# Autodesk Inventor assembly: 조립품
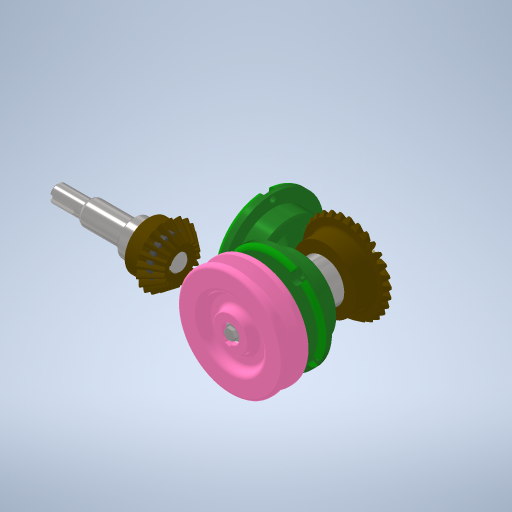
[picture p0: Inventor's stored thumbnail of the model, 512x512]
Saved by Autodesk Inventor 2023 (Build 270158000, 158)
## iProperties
Created: 2023-12
Part Number: 조립품
Document SubType Name: Assembly
Designer: asung
Author: asung
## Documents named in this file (15)
- C:\Users\asung\Desktop\시험\조립품.iam
- C:\Users\asung\Desktop\시험\본체.ipt
- C:\Users\asung\Desktop\시험\메인 축.ipt
- 메인 축.ipt
- C:\Users\asung\Desktop\시험\베어링 6203.ipt
- C:\Users\asung\Desktop\시험\커버.ipt
- C:\Users\asung\Desktop\시험\오일실 17 x 32 x 8.ipt
- C:\Users\asung\Desktop\시험\키 5 x 5 x 14.ipt
- C:\Users\asung\Desktop\시험\메인 베벨기어.ipt
- C:\Users\asung\Desktop\시험\키 4 x 4 x 14.ipt
- C:\Users\asung\Desktop\시험\V-벨트풀리.ipt
- C:\Users\asung\Desktop\시험\육각볼트 M4 x 8.ipt
- C:\Users\asung\Desktop\시험\서브 베벨기어.ipt
- C:\Users\asung\Desktop\시험\서브 축.ipt
- 서브 축.ipt
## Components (1 placed, 1 different names)
1. V-벨트풀리:1
